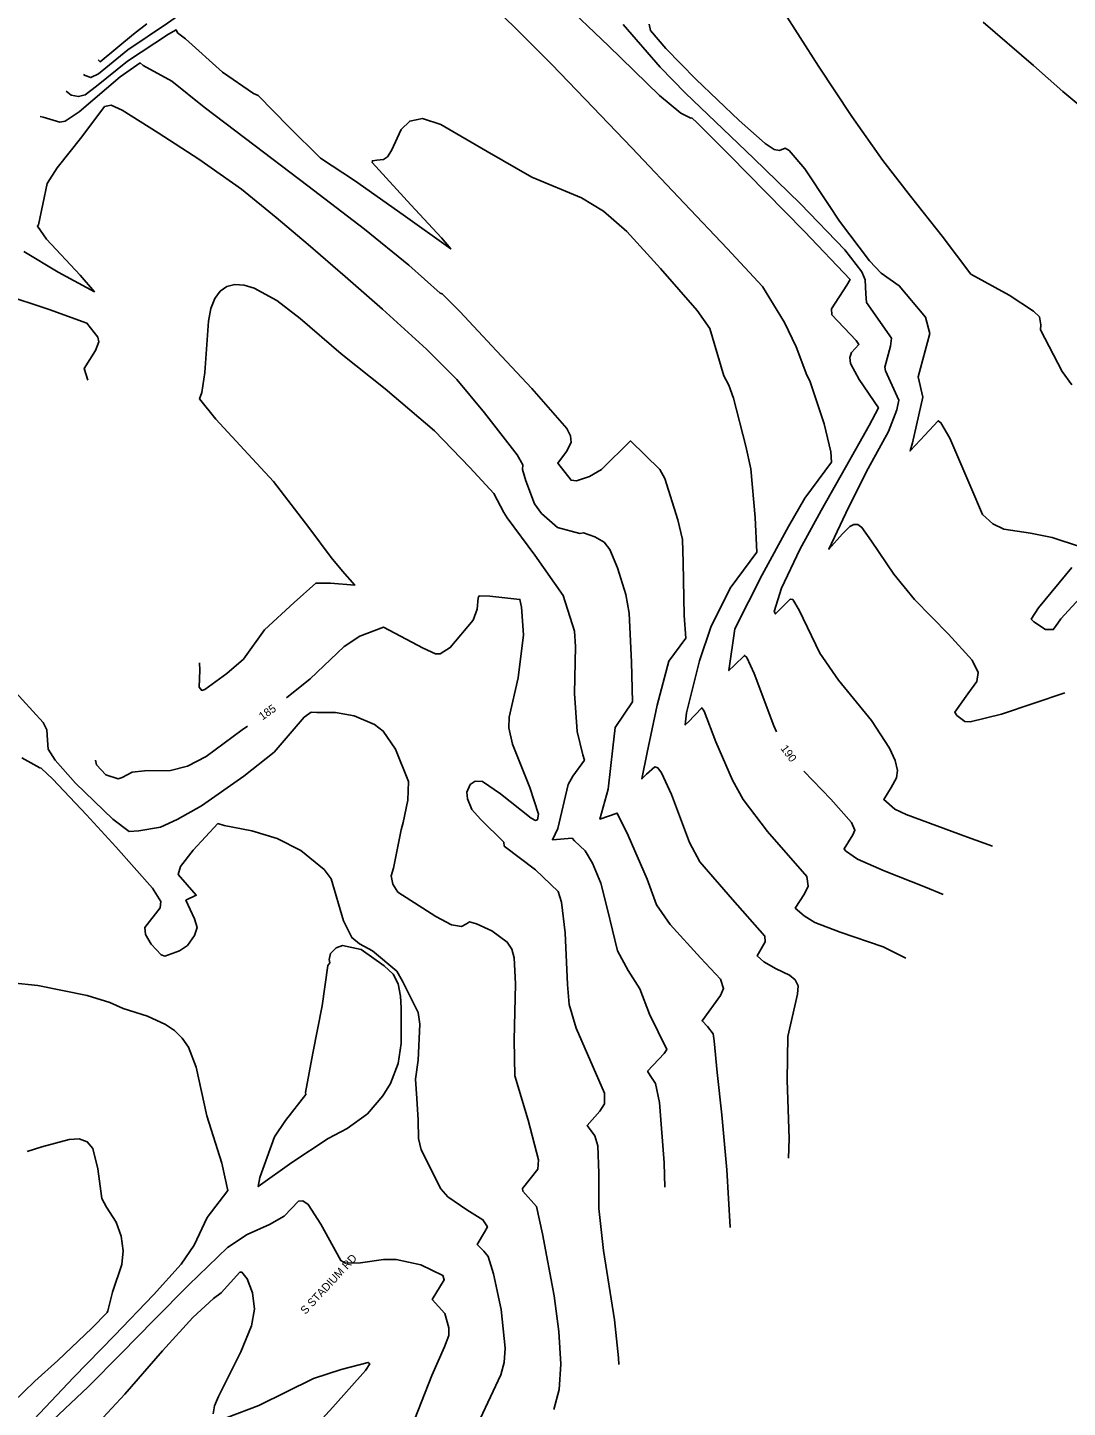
# Model space of a CAD drawing. Extents: x 1467615 to 2003689, y 770235 to 1108726.
# Drawn here: x 1993159.2 to 1993419.1, y 778248.4 to 778593.3 of the extents above; entities that cross this region are included whole.
import ezdxf

# ---------------------------------------------------------------- set-up
doc = ezdxf.new("R2010")
doc.units = 0
for name, color, linetype in [('RD_DTM_Major1', 7, 'Continuous'), ('RD_DTM_Major1_Lbl', 7, 'Continuous'), ('RD_DTM_Minor1', 7, 'Continuous'), ('RD_TX_Misc1', 7, 'Continuous')]:
    doc.layers.add(name, color=color, linetype=linetype)

msp = doc.modelspace()

# ---------------------------------------------------------------- linework, layer by layer
at = {"layer": 'RD_DTM_Major1'}
for points in [[(1993173.12, 778581.61), (1993173.53, 778581.29), (1993175, 778580.81), (1993176.87, 778581.73), (1993184.24, 778587.77), (1993194.16, 778594.39), (1993204.69, 778601.92), (1993212.78, 778609.32), (1993220.47, 778616.31), (1993230.25, 778624.96), (1993234.69, 778628.46), (1993235.3, 778627.97), (1993239.17, 778624.17), (1993243.06, 778621.19)], [(1993271.49, 778602.6), (1993280.94, 778593.29), (1993290.08, 778584.17), (1993298.56, 778575.42), (1993310.21, 778563.24), (1993323.29, 778549.44), (1993334.04, 778538.13), (1993342.86, 778528.62), (1993348.38, 778519.62), (1993351.23, 778513.55), (1993353.95, 778506.44), (1993354.66, 778505), (1993358.27, 778494.27), (1993359.95, 778487.26), (1993360.08, 778484.68), (1993353.41, 778475.72), (1993349.38, 778468.58), (1993342.77, 778456.49), (1993335.93, 778443.06), (1993334.46, 778432.62), (1993335.73, 778433.87), (1993338.33, 778436.39), (1993338.92, 778435.85), (1993340.79, 778431.89), (1993345.67, 778418.79), (1993346.36, 778417.28)], [(1993223.84, 778425.76), (1993229.78, 778430.53), (1993238.32, 778438.59), (1993242.2, 778441.24), (1993248.16, 778443.46), (1993258.02, 778438.2), (1993261.11, 778436.82), (1993262.26, 778436.76), (1993264.8, 778438.33), (1993270.51, 778445.2), (1993271.53, 778447.99), (1993271.78, 778450.81), (1993272.07, 778451.31), (1993274.74, 778451.23), (1993282.21, 778450.4), (1993282.64, 778448.43), (1993283.1, 778441.5), (1993281.75, 778430.81), (1993279.55, 778420.92), (1993279.47, 778418.3), (1993280.38, 778414.23), (1993284.67, 778403.4), (1993286.85, 778396.68), (1993286.58, 778395.3), (1993286.09, 778395.17), (1993285.02, 778395.69), (1993277.37, 778401.83), (1993272.88, 778404.86), (1993271, 778404.95), (1993269.75, 778404.12), (1993268.91, 778402.18), (1993269.1, 778400.56), (1993270.23, 778397.91), (1993272.36, 778395.5), (1993278.19, 778389.75), (1993278.26, 778388.73), (1993286.12, 778382.78), (1993291.82, 778377.36), (1993292.64, 778374.7), (1993293.57, 778367.05), (1993294.1, 778354.13), (1993294.54, 778349.16), (1993296.28, 778343.2), (1993300.56, 778333.52), (1993303.35, 778327), (1993303.38, 778324.32), (1993302.21, 778322.52), (1993299, 778318.88), (1993300, 778317.58), (1993300.92, 778316.32), (1993301.67, 778313.83), (1993301.93, 778307.02), (1993301.93, 778298.19), (1993303.14, 778287.65), (1993305.84, 778270.33), (1993306.87, 778260.82), (1993306.91, 778259.17)], [(1993176.13, 778410.2), (1993176.4, 778409.06), (1993178.75, 778406.54), (1993181.84, 778405.53), (1993182.82, 778405.89), (1993185.27, 778407.17), (1993188.42, 778407.57), (1993194.86, 778407.63), (1993199.11, 778408.67), (1993203.77, 778411.16), (1993212.82, 778417.78), (1993214.13, 778418.7)], [(1993353.22, 778407.43), (1993359.94, 778400.45), (1993365.06, 778394.61), (1993365.97, 778392.68), (1993365.46, 778391.57), (1993363.23, 778388.05), (1993363.63, 778387.58), (1993366.64, 778385.45), (1993373.24, 778382.53), (1993383.56, 778378.45), (1993388.03, 778376.66)]]:
    msp.add_lwpolyline(points, dxfattribs=at)
at = {"layer": 'RD_DTM_Minor1'}
for points in [[(1993292.3, 778600.3), (1993304.32, 778588.77), (1993317.07, 778576.35), (1993322.46, 778571.91), (1993324.9, 778570.64), (1993325.17, 778570.73), (1993326.5, 778569.54), (1993334.65, 778561.33), (1993343.67, 778552.15), (1993353.35, 778542.31), (1993364.75, 778530.32), (1993363.93, 778528.96), (1993360.12, 778523.05), (1993360.22, 778521.52), (1993366.3, 778515.06), (1993366.96, 778514.1), (1993365.07, 778512.08), (1993364.7, 778510.89), (1993364.86, 778509.35), (1993367.03, 778505.36), (1993371.84, 778498.28), (1993369.51, 778493.86), (1993363.6, 778483.35), (1993357.48, 778472.62), (1993352.16, 778462.89), (1993347.57, 778453.2), (1993345.78, 778447.39), (1993346.13, 778446.76), (1993347.58, 778448.32), (1993349.79, 778450.49), (1993350.41, 778450.33), (1993352.02, 778447.74), (1993357.15, 778436.93), (1993361.89, 778430.18), (1993370.14, 778420.13), (1993374.59, 778413.23), (1993376.03, 778410.1), (1993376.56, 778407.62), (1993376.36, 778405.76), (1993375.05, 778403.42), (1993373.17, 778400.36), (1993375.97, 778398), (1993378.79, 778396.67), (1993394.11, 778390.95), (1993400.31, 778388.68)], [(1993347.69, 778597.99), (1993356.85, 778583.66), (1993365.18, 778571.11), (1993372.96, 778560.07), (1993379.85, 778551.21), (1993387.77, 778541.14), (1993394.95, 778531.67), (1993404.52, 778526.42), (1993410.62, 778522.47), (1993412.05, 778520.99), (1993412.4, 778519.03), (1993412.3, 778517.74), (1993417.76, 778507.36), (1993420.16, 778503.98)], [(1993176.79, 778585.21), (1993177.32, 778584.76), (1993185.6, 778591.63), (1993188.93, 778594.28)], [(1993308.04, 778594.05), (1993317.27, 778583.4), (1993323.58, 778576.89), (1993331.1, 778569.78), (1993340.64, 778560.66), (1993352.35, 778549.26), (1993363.42, 778537.79), (1993367.69, 778532.28), (1993368.54, 778530.25), (1993368.7, 778526.79), (1993368.86, 778524.56), (1993375.08, 778515.72), (1993374.88, 778513.7), (1993373.44, 778508.47), (1993373.6, 778507.55), (1993376.97, 778500.16), (1993376.39, 778497.75), (1993374.34, 778492.39), (1993369.24, 778483.09), (1993364.35, 778473.34), (1993359.44, 778462.91), (1993362.87, 778466.74), (1993364.7, 778468.62), (1993365.68, 778469.15), (1993366.68, 778469.13), (1993367.71, 778468.38), (1993370.11, 778464.98), (1993375.7, 778456.71), (1993380.84, 778450.39), (1993389.38, 778441.7), (1993395.25, 778435.19), (1993396.72, 778432.15), (1993396.41, 778429.87), (1993394.17, 778426.78), (1993390.91, 778422.19), (1993391.42, 778421.38), (1993393.39, 778419.86), (1993394.72, 778419.81), (1993402.57, 778421.72), (1993418.4, 778427.03)], [(1993314.49, 778594.19), (1993314.88, 778592.57), (1993318.65, 778588.05), (1993326.17, 778580.45), (1993337.03, 778570.05), (1993343.56, 778564.35), (1993345.8, 778562.86), (1993347.12, 778562.56), (1993348.49, 778563.16), (1993349.51, 778562.61), (1993353.4, 778558), (1993359.38, 778549.13), (1993362.08, 778544.93), (1993369.59, 778535.02), (1993372.54, 778531.93), (1993377.04, 778528.77), (1993383.58, 778520.89), (1993384.69, 778516.86), (1993381.78, 778506.03), (1993382.97, 778500.94), (1993380.31, 778489.54), (1993379.74, 778487.52), (1993382.24, 778490.23), (1993386.77, 778495.04), (1993387.46, 778494.56), (1993389.69, 778490.69), (1993394.89, 778478.46), (1993397.82, 778471.63), (1993400.39, 778469.27), (1993403.2, 778467.97), (1993409.81, 778466.94), (1993415.26, 778465.86), (1993422.08, 778463.64)], [(1993423.9, 778572.32), (1993417.94, 778577.32), (1993410.57, 778583.82), (1993398.04, 778594.64)], [(1993168.81, 778577.38), (1993170.01, 778576.43), (1993171.85, 778576.05), (1993173.52, 778576.52), (1993176.42, 778578.7), (1993184.09, 778584.94), (1993194.4, 778591.69), (1993196.29, 778592.77), (1993196.6, 778592), (1993198.63, 778590.48), (1993207.89, 778582.15), (1993215.63, 778576.79), (1993216.81, 778576.37), (1993224.42, 778568.48), (1993232.37, 778560.64), (1993240.87, 778555.06), (1993253.02, 778546.51), (1993264.95, 778537.99), (1993262.6, 778540.75), (1993254.99, 778549.03), (1993245.32, 778559.6), (1993245.34, 778560.03), (1993246.45, 778560.2), (1993248.13, 778560.32), (1993249.14, 778561.01), (1993250.16, 778562.55), (1993252.57, 778567.81), (1993254.67, 778569.95), (1993257.89, 778570.57), (1993262.47, 778569.09), (1993274.01, 778562.31), (1993285.21, 778555.95), (1993297.57, 778550.73), (1993303.08, 778547.46), (1993308.97, 778542.33), (1993317.32, 778533.11), (1993326.56, 778522.56), (1993329.66, 778518.13), (1993333.23, 778506.3), (1993334.43, 778503.94), (1993335.62, 778500.69), (1993338.69, 778488.68), (1993339.95, 778483.06), (1993340.99, 778470.83), (1993341.4, 778462.21), (1993334.75, 778453.22), (1993329.95, 778443.46), (1993327.12, 778435), (1993323.87, 778422.04), (1993323.53, 778419.04), (1993324.26, 778419.72), (1993327.66, 778423.3), (1993328.25, 778422.44), (1993331.17, 778414.77), (1993335.35, 778405.25), (1993338.04, 778400.42), (1993344.14, 778392.36), (1993353.96, 778381.1), (1993354.29, 778378.72), (1993353.38, 778376.84), (1993351.04, 778373.23), (1993353.25, 778371.32), (1993355.92, 778369.63), (1993362.28, 778367.26), (1993373.05, 778363.57), (1993378.7, 778360.74)], [(1993162.34, 778571.05), (1993163.01, 778570.9), (1993167.21, 778569.69), (1993168.56, 778569.91), (1993172.03, 778572.24), (1993182.32, 778580.98), (1993187.26, 778584.47), (1993188.02, 778583.84), (1993195.2, 778579.95), (1993203.32, 778573.45), (1993213.61, 778565.55), (1993229.18, 778553.72), (1993243.41, 778542.92), (1993254.47, 778533.93), (1993262.32, 778526.93), (1993262.8, 778526.79), (1993267.22, 778522.38), (1993276.4, 778512.5), (1993285.21, 778503.07), (1993293.96, 778493.11), (1993294.88, 778491.23), (1993295.04, 778489.64), (1993293.9, 778487.34), (1993291.68, 778484.45), (1993294.99, 778480.19), (1993296.38, 778480.05), (1993299.6, 778481.09), (1993302.57, 778482.82), (1993309.9, 778490.02), (1993317.17, 778482.83), (1993318.4, 778480.57), (1993321.67, 778470.31), (1993322.86, 778465.38), (1993323.05, 778459.61), (1993323.29, 778446.33), (1993323.65, 778440.72), (1993319.45, 778434.93), (1993316.49, 778423.95), (1993314.02, 778412.16), (1993312.7, 778405.52), (1993313.89, 778406.7), (1993315.9, 778408.56), (1993316.66, 778408.26), (1993317.62, 778407.04), (1993320.11, 778401.59), (1993324.62, 778389.66), (1993327.2, 778384.81), (1993335.34, 778375.35), (1993343.43, 778366.26), (1993343.51, 778364.77), (1993341.52, 778361.27), (1993343.15, 778359.82), (1993346.25, 778358.03), (1993349.61, 778356.48), (1993351, 778355.34), (1993351.74, 778353.79), (1993351.6, 778351.71), (1993349.15, 778341.13), (1993349.03, 778330.25), (1993349.5, 778315.62), (1993349.38, 778310.75)], [(1993158.23, 778537.38), (1993166.81, 778532.21), (1993175.87, 778527.28), (1993172.3, 778531.44), (1993163.92, 778540.41), (1993161.62, 778543.69), (1993161.86, 778544), (1993164.02, 778554.32), (1993166.55, 778558.23), (1993172.74, 778566.04), (1993178.42, 778573.57), (1993180.07, 778573.91), (1993182.77, 778572.68), (1993191.83, 778567.02), (1993201.92, 778560.43), (1993212.59, 778552.96), (1993221.29, 778545.85), (1993229.29, 778539.08), (1993238.54, 778531.13), (1993247.87, 778522.94), (1993258.89, 778512.97), (1993266.47, 778505.33), (1993273.36, 778497.06), (1993281.57, 778486.5), (1993282.97, 778484.02), (1993282.84, 778482.84), (1993283.68, 778480), (1993285.9, 778474.3), (1993287.62, 778471.89), (1993291.58, 778468.37), (1993297.16, 778466.85), (1993298.07, 778466.99), (1993300.96, 778466.04), (1993303.25, 778464.7), (1993304.73, 778462.86), (1993306.6, 778458.26), (1993308.71, 778451.59), (1993309.5, 778446.96), (1993310.11, 778434.68), (1993310.37, 778424.83), (1993305.99, 778418.34), (1993305.41, 778413.32), (1993304.3, 778403), (1993302.22, 778395.43), (1993306.53, 778396.98), (1993309.25, 778391.36), (1993314.05, 778380.44), (1993316.38, 778374.06), (1993319.74, 778369.13), (1993327.34, 778360.79), (1993332.35, 778355.48), (1993333.13, 778353.17), (1993332.36, 778351.38), (1993327.76, 778345.04), (1993329.09, 778343.66), (1993330.52, 778341.79), (1993330.81, 778340.09), (1993331.54, 778332.18), (1993332.72, 778321.55), (1993333.92, 778307.78), (1993334.78, 778293.53), (1993334.78, 778293.45)], [(1993133.63, 778528.55), (1993141.53, 778523.01), (1993134.38, 778530.62), (1993128.73, 778536.83), (1993128.84, 778539.6), (1993129.36, 778539.5), (1993135.51, 778534.82), (1993144.9, 778529.78), (1993152.99, 778526.68), (1993164.54, 778522.85), (1993173.98, 778519.44), (1993176.69, 778515.92), (1993176.93, 778514.79), (1993176.13, 778512.57), (1993173.28, 778508.11), (1993174.19, 778505.19)], [(1993202.16, 778434.5), (1993202.25, 778432.69), (1993202.02, 778428.48), (1993202.68, 778427.66), (1993203.49, 778427.89), (1993208.94, 778431.83), (1993213.15, 778435.47), (1993218.34, 778442.82), (1993225.76, 778449.63), (1993231.18, 778454.41), (1993234.91, 778454.47), (1993240.95, 778453.91), (1993237.89, 778457.47), (1993235.02, 778460.87), (1993229.44, 778468.33), (1993220.61, 778479.87), (1993214.29, 778486.72), (1993206.25, 778495.42), (1993202.15, 778500.52), (1993202.67, 778502.08), (1993203.46, 778507.06), (1993204.39, 778519.96), (1993205, 778523.06), (1993205.96, 778525.56), (1993207.29, 778527.39), (1993208.96, 778528.56), (1993210.96, 778529.06), (1993213.26, 778528.92), (1993215.8, 778528.17), (1993221.43, 778525.11), (1993227.27, 778520.59), (1993237.52, 778511.74), (1993248.54, 778503.04), (1993260.84, 778492.49), (1993269.69, 778483.34), (1993275.66, 778476.88), (1993278.21, 778472.09), (1993279.02, 778470.8), (1993285.91, 778461.45), (1993293, 778451.37), (1993295.89, 778442.44), (1993296.08, 778438.58), (1993295.89, 778426.87), (1993296.56, 778417.36), (1993297.97, 778411.52), (1993298.36, 778410.2), (1993295.45, 778406.22), (1993294.24, 778404.11), (1993291.72, 778393.17), (1993290.34, 778390.32), (1993295.24, 778390.74), (1993295.87, 778390.07), (1993298.49, 778387.58), (1993300.35, 778384.5), (1993302.43, 778379.51), (1993304.14, 778372.91), (1993306.63, 778362.55), (1993309.24, 778357.6), (1993312.18, 778353.08), (1993314.59, 778346.71), (1993318.9, 778337.88), (1993318.25, 778336.86), (1993314.11, 778332.51), (1993314.77, 778331.42), (1993316.11, 778329.43), (1993317.14, 778324.67), (1993318.29, 778309.59), (1993318.44, 778303.46)], [(1993420.19, 778458.4), (1993411.88, 778448.31), (1993410.01, 778445.42), (1993410.64, 778444.77), (1993413.6, 778442.85), (1993415.54, 778442.85), (1993416.1, 778443.59), (1993417.44, 778445.55), (1993425.01, 778453.81)], [(1993155.28, 778428.13), (1993163.01, 778419.66), (1993163.99, 778417.81), (1993164.14, 778415.19), (1993164.33, 778412.94), (1993166.03, 778410.2), (1993171.17, 778404.49), (1993180.46, 778395.48), (1993184.55, 778392.36), (1993187, 778392.55), (1993192.34, 778393.47), (1993196.57, 778395.37), (1993202.63, 778398.83), (1993213.2, 778406.18), (1993220.77, 778412.25), (1993228.25, 778420.92), (1993230.04, 778422.19), (1993231.46, 778422.11), (1993236.09, 778422.15), (1993240.81, 778421.33), (1993245.88, 778419.16), (1993248.07, 778417.46), (1993251.13, 778413), (1993254.34, 778404.88), (1993254.24, 778400.24), (1993253.01, 778394.62), (1993252.54, 778392.78), (1993250.66, 778383.21), (1993250.04, 778381.32), (1993250.45, 778379.22), (1993251.74, 778377.24), (1993261.19, 778371.12), (1993265.13, 778369.05), (1993267.59, 778368.66), (1993268.89, 778369.27), (1993269.61, 778369.79), (1993271.4, 778369.3), (1993275.22, 778367.58), (1993279.04, 778364.75), (1993280.19, 778362.96), (1993280.81, 778360.77), (1993281.08, 778354.32), (1993280.8, 778340.22), (1993280.95, 778331.3), (1993284.25, 778320.25), (1993286.84, 778310.3), (1993286.66, 778308), (1993282.88, 778303.16), (1993282.95, 778302.48), (1993286.36, 778298.65), (1993287.88, 778291.83), (1993290.74, 778276.33), (1993291.94, 778267.39), (1993292.46, 778259.27), (1993292, 778252.88), (1993290.71, 778247.89)], [(1993157.74, 778410.78), (1993162.24, 778408.27), (1993162.59, 778408.21), (1993165.43, 778405.45), (1993173.87, 778396.53), (1993181.2, 778388.56), (1993190.39, 778378.23), (1993192.45, 778374.92), (1993192.32, 778373.33), (1993188.47, 778368.42), (1993188.59, 778366.64), (1993190.04, 778364.21), (1993192.52, 778361.53), (1993193.45, 778361.23), (1993197.12, 778362.59), (1993199.1, 778363.87), (1993200.9, 778366.36), (1993201.54, 778368.36), (1993200.91, 778370.56), (1993198.73, 778375.18), (1993201.3, 778376.45), (1993196.81, 778381.63), (1993197.41, 778383.67), (1993200.55, 778387.74), (1993206.68, 778394.37), (1993208.3, 778393.88), (1993215.25, 778392.51), (1993221.52, 778390.64), (1993227.46, 778387.64), (1993233.26, 778382.86), (1993235.04, 778380.56), (1993238.16, 778370.06), (1993240.24, 778365.85), (1993242.14, 778364.28), (1993245.36, 778362.57), (1993251.45, 778357.51), (1993252.89, 778354.99), (1993256.76, 778347.14), (1993257.19, 778344.26), (1993256.78, 778335.22), (1993256.1, 778330.52), (1993256.45, 778325.61), (1993256.75, 778320.22), (1993256.85, 778315.62), (1993257.54, 778312.78), (1993262.49, 778303.06), (1993264.2, 778301.11), (1993268.92, 778297.83), (1993272.99, 778295.35), (1993274.11, 778293.56), (1993273.4, 778292.22), (1993271.54, 778289.17), (1993273.24, 778287.5), (1993274.25, 778286.18), (1993275.65, 778281.86), (1993277.5, 778272.92), (1993278.51, 778263.28), (1993278.24, 778259.65), (1993277.42, 778256.62), (1993272.3, 778245.57)], [(1993252.36, 778351.26), (1993251.79, 778354.34), (1993250.55, 778356.7), (1993248.26, 778358.84), (1993242.52, 778362.9), (1993237.87, 778363.87), (1993236.3, 778363.34), (1993234.91, 778361.92), (1993234.58, 778360.4), (1993234.67, 778359.52), (1993234.21, 778358.86), (1993232.76, 778348.82), (1993230.42, 778337), (1993228.64, 778327.19), (1993228.7, 778326.63), (1993223.59, 778320.14), (1993220.84, 778316.09), (1993217.18, 778305.9), (1993216.82, 778303.62), (1993225.21, 778309.68), (1993234.3, 778315.66), (1993239.01, 778318.16), (1993244.09, 778321.82), (1993247.95, 778326.28), (1993249.87, 778329.37), (1993251.81, 778334.37), (1993252.54, 778339.37), (1993252.55, 778348.33), (1993252.36, 778351.26)], [(1993155.3, 778354.53), (1993161.68, 778353.88), (1993174.07, 778351.39), (1993179.7, 778349.62), (1993183.07, 778348.16), (1993189.12, 778346.24), (1993193.59, 778344.15), (1993195.85, 778342.64), (1993197.83, 778340.74), (1993199.38, 778338.44), (1993201.3, 778333.48), (1993203.96, 778321.34), (1993207.74, 778309.48), (1993209.17, 778302.62), (1993204.05, 778295.94), (1993200.83, 778289), (1993197.54, 778284.26), (1993190.6, 778276.57), (1993180.85, 778266.41), (1993170.72, 778255.98), (1993160.71, 778245.4)], [(1993159.09, 778312.42), (1993162.69, 778313.54), (1993169.54, 778315.44), (1993172.02, 778315.53), (1993174.07, 778314.82), (1993175.45, 778313.13), (1993176.69, 778308.1), (1993177.71, 778300.67), (1993178.86, 778298.46), (1993181.27, 778294.71), (1993182.51, 778291.27), (1993183.04, 778287.56), (1993182.68, 778284.16), (1993180.4, 778277.21), (1993179.24, 778272.6), (1993179.04, 778272.14), (1993175.21, 778268.26), (1993166.75, 778260.13), (1993160.93, 778255), (1993155.51, 778249.69)], [(1993165.56, 778245.34), (1993174.3, 778253.57), (1993182.58, 778261.91), (1993190.8, 778270.33), (1993199.47, 778279.07), (1993209.11, 778288.43), (1993214.01, 778291.66), (1993219.62, 778294.14), (1993223.25, 778296.28), (1993226.85, 778299.96), (1993227.98, 778300.04), (1993229.3, 778299.16), (1993232.42, 778294.27), (1993237.43, 778285.12), (1993238.6, 778284.47), (1993242.38, 778284.61), (1993248.08, 778285.41), (1993251.27, 778285.43), (1993257.43, 778284.08), (1993262.97, 778281.4), (1993263.31, 778280.35), (1993260.3, 778275.41), (1993263.43, 778271.89), (1993264.49, 778268.32), (1993264.47, 778266.41), (1993263.37, 778263.61), (1993260.22, 778256.42), (1993255.03, 778243.26)], [(1993174.79, 778242.44), (1993183.45, 778251.76), (1993192.85, 778262.62), (1993200.47, 778270.9), (1993205.66, 778275.7), (1993207.57, 778277.04), (1993212.18, 778282.21), (1993212.72, 778282.21), (1993214.05, 778280.59), (1993215.4, 778277.12), (1993215.86, 778273.02), (1993215.1, 778268.84), (1993212.44, 778262.36), (1993206.91, 778251.2), (1993205.88, 778248.82), (1993205.55, 778246.82)], [(1993209.05, 778245.92), (1993216.95, 778248.89), (1993230.59, 778255.64), (1993237.5, 778257.92), (1993244.29, 778259.67), (1993244.67, 778259.37), (1993243.66, 778257.69), (1993235.42, 778248.49), (1993231.96, 778244.69)]]:
    msp.add_lwpolyline(points, dxfattribs=at)

# ---------------------------------------------------------------- texts
at = {"layer": 'RD_DTM_Major1_Lbl'}
for s, rotation, p in [('185', 35.2454, (1993217.85, 778420.1)), ('190', 306.1114, (1993347.29, 778413.13))]:
    msp.add_text(s, height=2, rotation=rotation, dxfattribs=at).set_placement(p)
at = {"layer": 'RD_TX_Misc1'}
msp.add_text('S STADIUM RD', height=2, rotation=47.1886, dxfattribs=at).set_placement((1993228.62, 778271.56))

doc.saveas('drawing.dxf')
